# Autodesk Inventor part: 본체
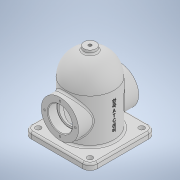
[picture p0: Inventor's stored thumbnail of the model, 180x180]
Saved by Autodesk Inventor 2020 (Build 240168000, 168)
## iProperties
Created: 2021-07
Part Number: 본체
Material: 일반
Document SubType Name: Modeling
Designer: Owner
Mass: 320.706 g
Surface Area: 800.746 cm^2
Volume: 320.706 cm^3
Density: 1 g/cm^3
Appearance: 기본값
Author: Owner
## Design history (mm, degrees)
sketch "스케치1"
  geometry: C1 r 40 at (0, 0); 1 further point
  constraints: 1 centre point, 1 coincident
  dimensions: "d0" = 80 diameter of C1
extrude "돌출1" new body sketch "스케치1" distance "d1" = 124; taper "d2" = 0 deg
fillet "모깎기1" dims "d3" = 40
feature "쉘1" dims "d4" = 8
sketch "스케치2"
  geometry: L1 (55, 55)-(-55, 55); L2 (-55, 55)-(-55, -55); L3 (-55, -55)-(55, -55); L4 (55, -55)-(55, 55); L5 (55, 55)-(-55, -55); L6 (-55, 55)-(55, -55); C1 r 32 at (0, 0) reference; 1 further point
  constraints: 12 end point, 2 midpoint, 2 parallel, 1 horizontal, 1 perpendicular
  dimensions: "d5" = 110 distance of L3.end L2.end; "d6" = 110 distance of L2.end L1.end
extrude "돌출2" join sketch "스케치2" distance "d7" = 10; taper "d8" = 0 deg
fillet "모깎기2" dims "d9" = 12
fillet "모깎기3" dims "d10" = 3
node "작업 평면1"
sketch "스케치3"
  geometry: C1 r 10 at (0, 0); 1 further point
  constraints: 1 centre point, 1 coincident
  dimensions: "d12" = 20 diameter of C1
extrude "돌출3" join sketch "스케치3" stored distance "d13" = 124; taper "d14" = 0 deg
sketch "스케치4"
  geometry: C1 r 10 at (0, 0) reference; 2 further points
  constraints: 1 coincident
hole "구멍1" sketch "스케치4" at (0, 0) diameter "d15" = 5.1881; stored, may be unused: countersink angle "d19" = 90 deg, drill point angle "d21" = 118 deg; dims "d16" = 30, "d17" = 8, "d18" = 10, "d20" = 16
node "작업 평면2"
sketch "스케치5"
  geometry: L1 (43, 0)-(-43, 0) reference; C1 r 31 at (0, 48); 2 further points
  constraints: 1 centre point, 1 midpoint, 1 vertical alignment
  dimensions: "d23" = 62 diameter of C1; "d24" = 48 distance from line of L1 C1.centre
extrude "돌출4" join sketch "스케치5" stored distance "d25" = 124; taper "d26" = 0 deg
sketch "스케치6"
  geometry: C1 r 31 at (0, 0) reference; 2 further points
  constraints: 1 coincident
hole "구멍2" sketch "스케치6" at (0, 0) diameter "d27" = 33; stored, may be unused: countersink angle "d31" = 90 deg, drill point angle "d33" = 118 deg; dims "d28" = 12, "d29" = 40, "d30" = 15, "d32" = 16
sketch "스케치7"
  geometry: L1 (43, -48)-(-43, -48) reference; C1 r 16.5 at (0, 0) reference; 3 further points
  constraints: 1 midpoint, 1 vertical alignment
  dimensions: "d34" = 25.5 distance of C1.centre point (0, 25.5)
hole "구멍3" sketch "스케치7" at (0, 25.5) diameter "d35" = 3.242; stored, may be unused: countersink angle "d39" = 90 deg, drill point angle "d41" = 118 deg; dims "d36" = 8, "d37" = 40, "d38" = 15, "d40" = 10
sketch "스케치8"
  geometry: A1 r 9 centre (-43, 43) between (-43, 52) and (-52, 43) reference; 2 further points
  constraints: 1 coincident
hole "구멍4" sketch "스케치8" at (-43, 43) diameter "d45" = 9; stored, may be unused: countersink angle "d49" = 90 deg, drill point angle "d51" = 118 deg; dims "d46" = 8, "d47" = 40, "d48" = 15, "d50" = 10
sketch "스케치9"
  geometry: A1 r 9 centre (43, 43) between (52, 43) and (43, 52) reference; 2 further points
  constraints: 1 coincident
hole "구멍5" sketch "스케치9" at (43, 43) diameter "d52" = 9; stored, may be unused: countersink angle "d56" = 90 deg, drill point angle "d58" = 118 deg; dims "d53" = 8, "d54" = 40, "d55" = 15, "d57" = 10
sketch "스케치10"
  geometry: A1 r 9 centre (-43, -43) between (-52, -43) and (-43, -52) reference; 2 further points
  constraints: 1 coincident
hole "구멍6" sketch "스케치10" at (-43, -43) diameter "d59" = 9; stored, may be unused: countersink angle "d63" = 90 deg, drill point angle "d65" = 118 deg; dims "d60" = 8, "d61" = 40, "d62" = 15, "d64" = 10
sketch "스케치11"
  geometry: A1 r 9 centre (43, -43) between (43, -52) and (52, -43) reference; 2 further points
  constraints: 1 coincident
hole "구멍7" sketch "스케치11" at (43, -43) diameter "d66" = 9; stored, may be unused: countersink angle "d70" = 90 deg, drill point angle "d72" = 118 deg; dims "d67" = 8, "d68" = 40, "d69" = 15, "d71" = 10
fillet "모깎기4" dims "d73" = 3
chamfer "모따기1" distance "d74" = 1; stored, may be unused: second distance "d75" = 2, angle "d76" = 45 deg
fillet "모깎기5" dims "d77" = 0.3
node "작업 평면3"
sketch "스케치12"
  geometry: L1 (0, -43)-(0, 43) reference; 3 further points
  constraints: 1 horizontal alignment, 1 midpoint, 1 other
  dimensions: "d79" = 48 distance from line of L1 point (48, 0)
feature "엠보싱1" sketch "스케치12" dims "d1" = 124, "d2" = 0, "d10" = 3, "d80" = 0.5, "d81" = 0
node "솔리드1"
mirror "미러1"
pattern_circular "원형 패턴1" dims angle "d43" = 360 deg
mirror "미러2"
feature "A9D066F2-1C7D-4E18-AEED-F7BC21143FA4" dims "d15" = 5.1881, "d16" = 30, "d17" = 8, "d18" = 10, "d19" = 90 deg, "d20" = 16, "d21" = 118 deg
other parameters: "d11" = 129
